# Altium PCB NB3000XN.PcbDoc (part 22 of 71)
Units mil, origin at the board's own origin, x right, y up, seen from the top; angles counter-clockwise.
Board outline 9527.56 x 6929.77 mil, 6 copper layers (Top Layer, GND+SHIELD, MidLayer1, MidLayer2, P2 - 3V3+5V0, Bottom Layer), stack 62.375 mil thick; 832 components, 1027 nets, 4655 pads, 4981 vias.
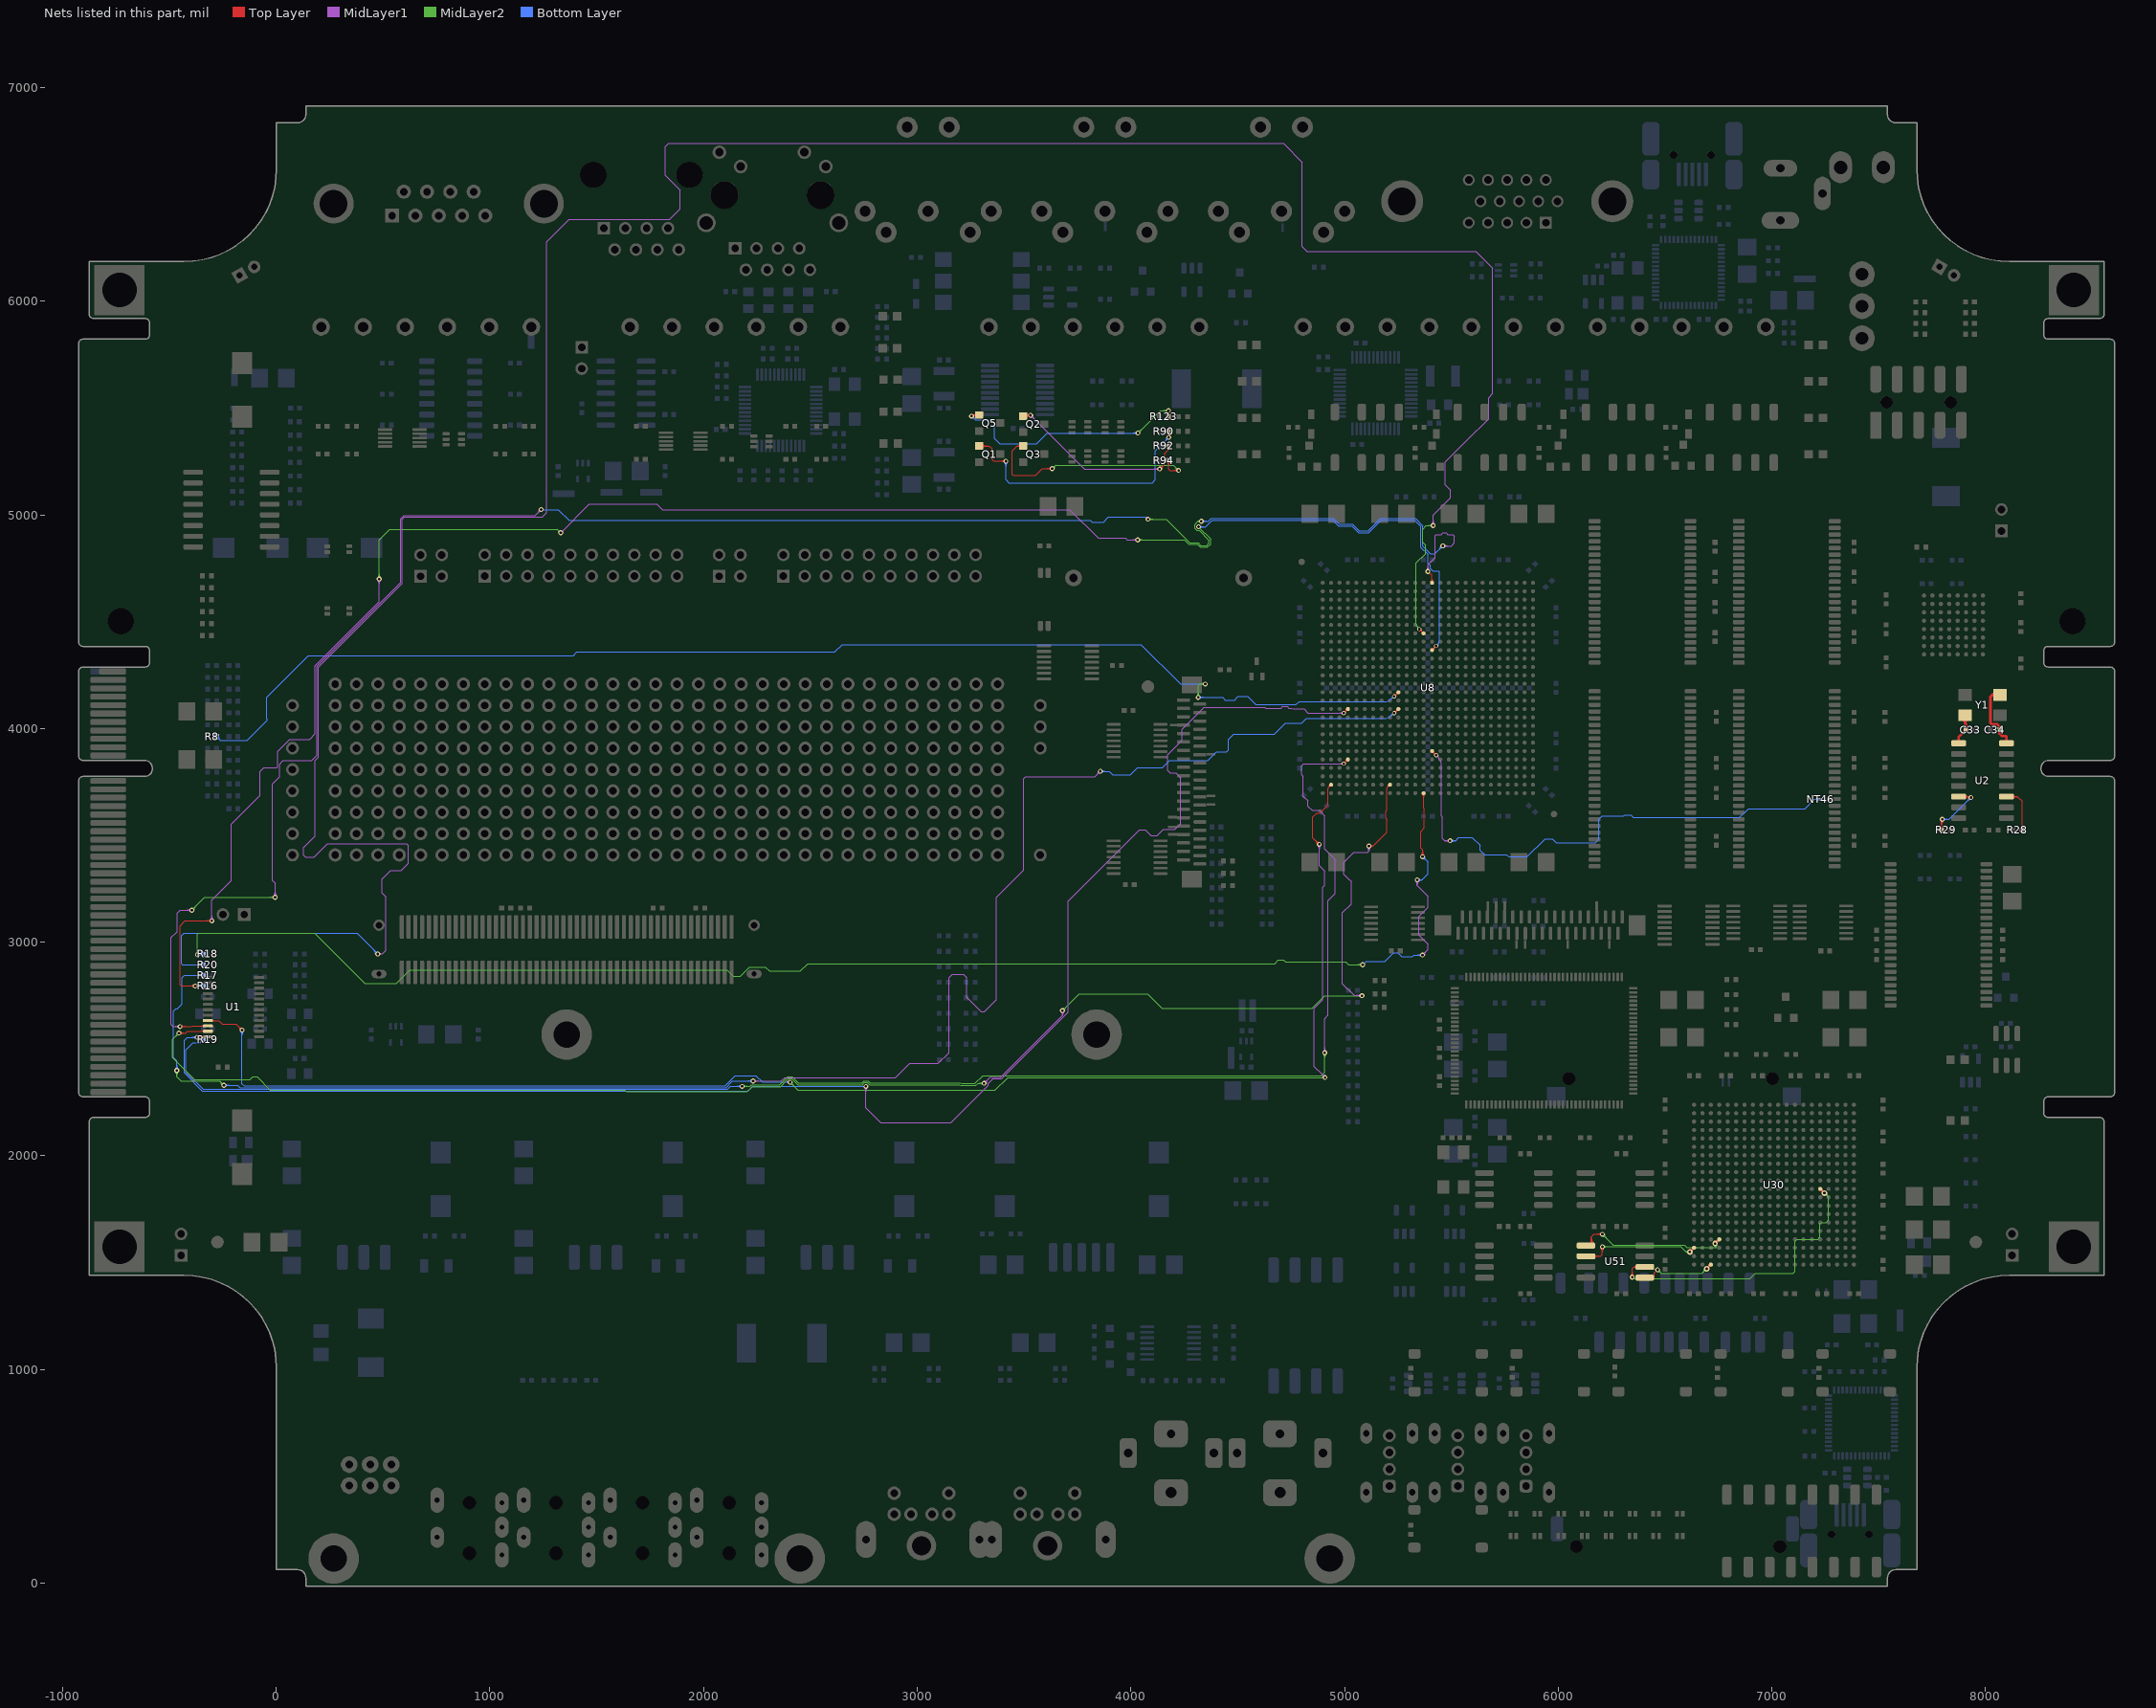
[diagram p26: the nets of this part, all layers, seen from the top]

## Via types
v1: diameter 23, hole 11.81, Top Layer to Bottom Layer, 3672 vias
v2: diameter 26, hole 11.81, Top Layer to Bottom Layer, 461 vias
v3: diameter 19, hole 11.81, Top Layer to Bottom Layer, tented both sides, 396 vias
v4: diameter 23.62, hole 11.81, Top Layer to Bottom Layer, 288 vias
v5: diameter 20, hole 11.81, Top Layer to Bottom Layer, 91 vias
v6: diameter 23, hole 11.81, Top Layer to Bottom Layer, tented both sides, 50 vias
v7: diameter 31, hole 11.81, Top Layer to Bottom Layer, 15 vias
v8: diameter 27.56, hole 11.81, Top Layer to Bottom Layer, tented both sides, 4 vias
v9: diameter 29, hole 11.81, Top Layer to Bottom Layer, 3 vias
v10: diameter 21, hole 11.81, Top Layer to Bottom Layer, 1 vias

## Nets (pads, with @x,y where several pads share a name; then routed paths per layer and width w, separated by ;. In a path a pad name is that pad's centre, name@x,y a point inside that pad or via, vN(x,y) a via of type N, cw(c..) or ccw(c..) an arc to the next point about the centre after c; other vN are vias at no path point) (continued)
BASEA: Q5.1 R123.2 | length 1608.2
  Top Layer w4: v1(3254.52,5462.71) v1@3259.22,5467.4 ; v1@3255.58,5461.65 cw(c3269.48,5447.75) 3269.48,5467.4 ; v1@3258.41,5458.82 cw(c3279.13,5438.1) Q5.1@3279.13,5467.4 ; v1@3261.24,5455.99 cw(c3288.79,5428.44) Q5.1@3288.79,5467.4 ; v1@3261.24,5469.43 ccw(c3266.13,5474.31) 3266.13,5467.4 ; Q5.1@3277.02,5458.25 ccw(c3259.22,5445.5) v1@3259.22,5467.4 ; Q5.1@3277.02,5476.55 cw(c3259.22,5489.3) v1@3259.22,5467.4 ; Q5.1@3280.28,5460.58 ccw(c3267,5451.07) 3267,5467.4 ccw(c3267,5483.73) Q5.1@3280.28,5474.22 ; Q5.1@3290.79,5467.4 v1@3259.22,5467.4 ; R123.2@4169.59,5467.08 ccw(c4153.66,5483.01) v1@4176.19,5483.01 ; v1@4171.65,5479.7 cw(c4167.48,5472.05) 4176.19,5472.05 ; R123.2@4172.42,5464.25 ccw(c4163.32,5473.35) 4176.19,5473.35 ; R123.2@4176.18,5460 4176.18,5472.04 ; 4176.19,5473.31 ccw(c4189,5473.31) R123.2@4179.94,5464.25 ; v1@4176.19,5482.97 ccw(c4198.66,5482.97) R123.2@4182.77,5467.08 ; v1(4176.19,5488.04) 4176.19,5472.05 ; R123.2@4178.17,5469.6 cw(c4178.7,5472.05) 4176.19,5472.05 ; R123.2@4178.15,5469.6 cw(c4178.68,5472.04) 4176.18,5472.04 ; v1@4180.73,5479.7 ccw(c4184.9,5472.05) 4176.19,5472.05 ; 4176.18,5472.04 cw(c4173.68,5472.04) 4174.21,5469.6 ccw(c4173.68,5472.05) 4176.19,5472.05
  MidLayer2 w4: v1(4033.19,5383.37) 4137.86,5488.04 v1(4176.19,5488.04) ; v1@4033.19,5388.87 ccw(c4033.19,5402.15) 4042.58,5392.76 ccw(c4051.97,5383.37) v1@4038.69,5383.37 ; v1@4033.19,5392.87 ccw(c4033.19,5415.81) 4049.41,5399.59 ccw(c4065.63,5383.37) v1@4042.69,5383.37 ; v1@4169.47,5481.32 ccw(c4153.26,5465.11) 4153.26,5488.04 ccw(c4153.26,5510.98) v1@4169.47,5494.76 ; v1@4172.3,5484.15 ccw(c4162.91,5474.76) 4162.91,5488.04 ccw(c4162.91,5501.32) v1@4172.3,5491.93
  Bottom Layer w4: v1@3254.52,5453.21 cw(c3254.52,5430.27) 3270.74,5446.49 cw(c3286.96,5462.71) v1@3264.02,5462.71 ; v1@3254.52,5457.21 cw(c3254.52,5443.93) 3263.91,5453.32 cw(c3273.3,5462.71) v1@3260.02,5462.71 ; v1(3254.52,5462.71) 3272.23,5445 3345,5445 3361.76,5428.24 3361.76,5358.24 3385.72,5334.28 3559.28,5334.28 3608.37,5383.37 v1(4033.19,5383.37) ; v1@4026.47,5376.66 ccw(c4010.26,5360.44) 4010.26,5383.37 ccw(c4010.26,5406.31) v1@4026.47,5390.09 ; v1@4029.3,5379.49 ccw(c4019.91,5370.1) 4019.91,5383.37 ccw(c4019.91,5396.65) v1@4029.3,5387.26
BASEB: Q1.1 R90.2 | length 1645.7
  Top Layer w4: Q1.1@3290.79,5322.4 3337.6,5322.4 3350,5310 3350,5260 3358.29,5251.71 v1(3415.19,5251.71) v1@3414.19,5252.71 ; Q1.1@3297.23,5316.95 cw(c3310.4,5303.77) 3310.4,5322.4 cw(c3310.4,5341.03) Q1.1@3297.23,5327.86 ; Q1.1@3300.06,5314.12 cw(c3320.06,5294.12) 3320.06,5322.4 cw(c3320.06,5350.69) Q1.1@3300.06,5330.69 ; Q1.1@3302.88,5311.29 cw(c3329.71,5284.46) 3329.71,5322.4 cw(c3329.71,5360.34) Q1.1@3302.88,5333.51 ; v1@3408.47,5244.99 ccw(c3392.26,5228.77) 3392.26,5251.71 ccw(c3392.26,5274.64) v1@3408.47,5258.43 ; v1@3411.3,5247.82 ccw(c3401.91,5238.43) 3401.91,5251.71 ccw(c3401.91,5264.99) v1@3411.3,5255.6 ; R90.2@4169.59,5384.59 cw(c4153.68,5368.68) 4176.18,5368.68 cw(c4198.68,5368.68) R90.2@4182.77,5384.59 ; v1@4170.81,5369.43 ccw(c4157.83,5382.4) R90.2@4176.18,5382.4 ; R90.2@4172.42,5387.41 cw(c4163.34,5378.33) 4176.18,5378.33 cw(c4189.02,5378.33) R90.2@4179.94,5387.41 ; 4176.18,5379.23 ccw(c4194.04,5379.23) v1@4181.41,5366.6 ; R90.2@4176.18,5388.89 ccw(c4203.7,5388.89) v1@4184.24,5369.43 ; R90.2@4176.18,5391.67 4176.18,5364.05 v1(4177.52,5362.71)
  Bottom Layer w4: v1@3408.47,5244.99 cw(c3392.26,5228.77) 3415.19,5228.77 cw(c3438.13,5228.77) v1@3421.91,5244.99 ; v1@3411.3,5247.82 cw(c3401.91,5238.43) 3415.19,5238.43 cw(c3428.47,5238.43) v1@3419.08,5247.82 ; v1(3415.19,5251.71) 3415.19,5164.81 3429.81,5150.19 4099.81,5150.19 4115,5165.38 4115,5300.18 v1(4177.52,5362.71) ; v1@4168.02,5362.71 cw(c4145.09,5362.71) 4161.31,5346.49 cw(c4177.52,5330.27) v1@4177.52,5353.21 ; v1@4172.02,5362.71 cw(c4158.75,5362.71) 4168.14,5353.32 cw(c4177.52,5343.93) v1@4177.52,5357.21
BASEC: Q2.1 R92.2 | length 1203.4
  Top Layer w4: Q2.1@3495.79,5462.4 v1@3526.22,5462.4 ; Q2.1@3497.19,5462.4 ccw(c3497.19,5500.04) v1@3523.81,5473.43 ; Q2.1@3506.51,5455.88 cw(c3518.72,5447.7) 3518.72,5462.4 cw(c3518.72,5477.11) Q2.1@3506.51,5468.92 ; Q2.1@3506.85,5462.4 ccw(c3506.85,5490.38) v1@3526.64,5470.6 ; Q2.1@3509.83,5453.66 cw(c3526.22,5442.68) v1@3526.22,5462.4 ; Q2.1@3509.83,5471.15 ccw(c3526.22,5482.13) v1@3526.22,5462.4 ; 3516.51,5462.4 ccw(c3516.51,5480.72) v1@3529.46,5467.77 ; 3517.98,5462.4 cw(c3517.98,5454.17) v1@3523.81,5459.99 ; v1(3530.52,5466.71) v1@3526.22,5462.4 ; v1(4135.19,5215.04) 4158.19,5238.04 4158.19,5287.72 4176.18,5305.71 ; v1@4135.19,5220.54 ccw(c4135.19,5233.82) 4144.58,5224.43 ccw(c4153.97,5215.04) v1@4140.69,5215.04 ; v1@4135.19,5224.54 ccw(c4135.19,5247.48) 4151.41,5231.26 ccw(c4167.63,5215.04) v1@4144.69,5215.04 ; R92.2@4171.12,5315.02 cw(c4165.09,5305.71) 4176.18,5305.71 ; R92.2@4176.18,5323.33 4176.18,5305.71 ; R92.2@4181.24,5315.02 ccw(c4187.27,5305.71) 4176.18,5305.71
  MidLayer1 w4: v1@3530.52,5457.21 cw(c3530.52,5434.27) 3546.74,5450.49 cw(c3562.96,5466.71) v1@3540.02,5466.71 ; v1@3530.52,5461.21 cw(c3530.52,5447.93) 3539.91,5457.32 cw(c3549.3,5466.71) v1@3536.02,5466.71 ; v1(3530.52,5466.71) 3782.19,5215.04 v1(4135.19,5215.04) ; v1@4128.47,5208.32 ccw(c4112.26,5192.11) 4112.26,5215.04 ccw(c4112.26,5237.98) v1@4128.47,5221.76 ; v1@4131.3,5211.15 ccw(c4121.91,5201.76) 4121.91,5215.04 ccw(c4121.91,5228.32) v1@4131.3,5218.93
BASED: Q3.1 R94.2 | length 1413.2
  Top Layer w4: Q3.1@3481.24,5314.47 ccw(c3467.4,5306.37) 3467.4,5322.4 ; Q3.1@3481.24,5330.34 cw(c3467.4,5338.43) 3467.4,5322.4 ; Q3.1@3484.69,5316.49 ccw(c3474.38,5310.45) 3474.38,5322.4 ccw(c3474.38,5334.35) Q3.1@3484.69,5328.32 ; Q3.1@3495.79,5322.4 3467.4,5322.4 ; v1@3625.14,5209.99 ccw(c3608.92,5193.77) 3608.92,5216.71 ccw(c3608.92,5239.64) v1@3625.14,5223.43 ; v1@3627.97,5212.82 ccw(c3618.58,5203.43) 3618.58,5216.71 ccw(c3618.58,5229.99) v1@3627.97,5220.6 ; v1(3631.86,5216.71) 3586.71,5216.71 3555,5185 3450,5185 3445,5190 3445,5300 3467.4,5322.4 ; R94.2@4169.59,5247.92 cw(c4153.68,5232.01) 4176.18,5232.01 cw(c4198.68,5232.01) R94.2@4182.77,5247.92 ; R94.2@4172.42,5250.75 cw(c4163.34,5241.67) 4176.18,5241.67 cw(c4189.02,5241.67) R94.2@4179.94,5250.75 ; R94.2@4176.18,5255 4176.18,5213.82 4181.63,5208.37 v1(4223.52,5208.37) ; v1@4216.81,5201.66 ccw(c4200.59,5185.44) 4200.59,5208.37 ccw(c4200.59,5231.31) v1@4216.81,5215.09 ; v1@4219.64,5204.49 ccw(c4210.25,5195.1) 4210.25,5208.37 ccw(c4210.25,5221.65) v1@4219.64,5212.26
  MidLayer2 w4: v1(3631.86,5216.71) 3648.52,5233.37 4198.52,5233.37 v1(4223.52,5208.37) ; v1@3631.86,5222.21 ccw(c3631.86,5235.49) 3641.25,5226.1 ccw(c3650.64,5216.71) v1@3637.36,5216.71 ; v1@3631.86,5226.21 ccw(c3631.86,5249.14) 3648.07,5232.93 ccw(c3664.29,5216.71) v1@3641.36,5216.71 ; v1@4214.02,5208.37 ccw(c4191.09,5208.37) 4207.31,5224.59 ccw(c4223.52,5240.81) v1@4223.52,5217.87 ; v1@4218.02,5208.37 ccw(c4204.75,5208.37) 4214.14,5217.76 ccw(c4223.52,5227.15) v1@4223.52,5213.87
BOOT_FLASH.DIN: U30.V20 U51.5 | length 550.9
  Top Layer w4: U51.5@6405.59,1430 6449.79,1430 ; U51.5@6446.62,1427.45 cw(c6449.79,1426.75) 6449.79,1430 ; U51.5@6446.62,1432.55 ccw(c6449.79,1433.25) 6449.79,1430 ; v1(6465.19,1466.71) 6449.79,1451.31 6449.79,1430
  Top Layer w8: v2(6695.04,1471.3) U30.V20@6714.72,1490.98 ; v2@6695.04,1480.3 ccw(c6695.04,1502.03) 6710.4,1486.66 ccw(c6725.77,1471.3) v2@6704.04,1471.3 ; U30.V20@6708.88,1490.98 cw(c6694.78,1490.98) 6704.75,1481.01 cw(c6714.72,1471.04) U30.V20@6714.72,1485.14
  MidLayer2 w4: v1@6465.19,1457.21 cw(c6465.19,1434.27) 6481.41,1450.49 cw(c6497.63,1466.71) v1@6474.69,1466.71 ; v1@6465.19,1461.21 cw(c6465.19,1447.93) 6474.58,1457.32 cw(c6483.97,1466.71) v1@6470.69,1466.71 ; v1(6465.19,1466.71) 6481.86,1450.04 6673.78,1450.04 v2(6695.04,1471.3) ; 6683.09,1459.35 ccw(c6671.14,1471.3) v2@6688.04,1471.3 ; 6683.09,1459.35 cw(c6695.04,1447.4) v2@6695.04,1464.3 ; v2@6684.04,1471.3 cw(c6657.48,1471.3) 6676.26,1452.52 cw(c6695.04,1433.75) v2@6695.04,1460.3
BOOT_FLASH.DOUT: U30.Y18 U51.2 | length 828.4
  Top Layer w4: U51.2@6130,1530 6200,1530 6206.86,1536.86 v1(6206.86,1574.37) ; U51.2@6165.03,1524.5 cw(c6178.31,1511.22) 6178.31,1530 cw(c6178.31,1548.78) U51.2@6165.03,1535.5 ; U51.2@6167.86,1521.67 cw(c6187.97,1501.56) 6187.97,1530 cw(c6187.97,1558.44) U51.2@6167.86,1538.33 ; v1@6200.14,1567.66 cw(c6183.92,1551.44) 6206.86,1551.44 cw(c6229.79,1551.44) v1@6213.57,1567.66 ; v1@6202.97,1570.49 cw(c6193.58,1561.1) 6206.86,1561.1 cw(c6220.14,1561.1) v1@6210.75,1570.49
  Top Layer w8: v2(6616.3,1550.04) U30.Y18@6635.98,1569.72 ; v2@6616.3,1559.04 ccw(c6616.3,1580.77) 6631.66,1565.4 ccw(c6647.03,1550.04) v2@6625.3,1550.04 ; U30.Y18@6630.14,1569.72 cw(c6616.04,1569.72) 6626.01,1559.75 cw(c6635.98,1549.78) U30.Y18@6635.98,1563.88
  MidLayer2 w4: v1(6206.86,1574.37) 6574.19,1574.37 6598.52,1550.04 ; v1@6210.75,1570.49 cw(c6220.14,1561.1) 6220.14,1574.37 cw(c6220.14,1587.65) v1@6210.75,1578.26 ; v1@6213.57,1567.66 cw(c6229.79,1551.44) 6229.79,1574.37 cw(c6229.79,1597.31) v1@6213.57,1581.09 ; v2@6606.45,1545.13 ccw(c6598.52,1541.18) 6598.52,1550.04 ; v2@6606.45,1554.95 cw(c6598.52,1558.9) 6598.52,1550.04 ; v2(6616.3,1550.04) 6598.52,1550.04
BOOT_FLASH.FLASH_CS_N: U30.U17 U51.1 | length 1022.1
  Top Layer w4: U51.1@6130,1580 6154.52,1580 6154.52,1619.52 ; U51.1@6151.2,1588.33 ccw(c6143.17,1596.36) 6154.52,1596.36 ; 6154.52,1600.68 ccw(c6179.49,1600.68) U51.1@6162.15,1582.72 ; 6154.52,1610.1 ccw(c6188.58,1610.1) U51.1@6164.93,1585.6 ; U51.1@6167.71,1588.48 cw(c6197.67,1619.52) 6154.52,1619.52 ; v1@6200.14,1626.66 ccw(c6183.92,1610.44) 6183.92,1633.37 ccw(c6183.92,1656.31) v1@6200.14,1640.09 ; v1@6202.97,1629.49 ccw(c6193.58,1620.1) 6193.58,1633.37 ccw(c6193.58,1646.65) v1@6202.97,1637.26 ; v1(6206.86,1633.37) 6168.37,1633.37 6154.52,1619.52
  Top Layer w8: v2(6734.41,1589.41) U30.U17@6754.09,1609.09 ; v2@6734.41,1598.41 ccw(c6734.41,1620.14) 6749.77,1604.77 ccw(c6765.14,1589.41) v2@6743.41,1589.41 ; U30.U17@6748.25,1609.09 cw(c6734.15,1609.09) 6744.12,1599.12 cw(c6754.09,1589.15) U30.U17@6754.09,1603.25
  MidLayer2 w4: v1@6206.86,1623.87 cw(c6206.86,1600.94) 6223.07,1617.16 cw(c6239.29,1633.37) v1@6216.36,1633.37 ; v1@6206.86,1627.87 cw(c6206.86,1614.6) 6216.25,1623.99 cw(c6225.64,1633.37) v1@6212.36,1633.37 ; v1(6206.86,1633.37) 6257.52,1582.71 6590.19,1582.71 6602.86,1570.04 6738.52,1570.04 6740.19,1571.71 6740.19,1589.41 v2(6734.41,1589.41) ; v2@6733.27,1578.47 cw(c6732.47,1570.79) 6740.19,1570.79 ; v2@6733.68,1582.45 cw(c6732.93,1575.23) 6740.19,1575.23 ; 6740.19,1576.81 cw(c6747.01,1576.81) v2@6742.19,1581.63
BOOT_FLASH.SCLK: U30.E11 U51.6 | length 1649.6
  Top Layer w4: v1@6339.47,1439.09 ccw(c6323.26,1455.31) 6346.19,1455.31 ccw(c6369.13,1455.31) v1@6352.91,1439.09 ; v1@6342.3,1436.26 ccw(c6332.91,1445.65) 6346.19,1445.65 ccw(c6359.47,1445.65) v1@6350.08,1436.26 ; v1(6346.19,1432.37) 6346.19,1472 6354.19,1480 ; U51.6@6366.23,1473.52 ccw(c6354.19,1465.58) 6354.19,1480 ; U51.6@6366.23,1486.48 cw(c6354.19,1494.42) 6354.19,1480 ; U51.6@6369.57,1475.72 ccw(c6361.62,1470.48) 6361.62,1480 ccw(c6361.62,1489.52) U51.6@6369.57,1484.28 ; U51.6@6405.59,1480 6354.19,1480
  Top Layer w8: U30.E11@7226.54,1839.47 cw(c7226.54,1825.37) 7236.51,1835.34 cw(c7246.48,1845.31) U30.E11@7232.38,1845.31 ; U30.E11@7226.54,1845.31 v2(7246.22,1825.63) ; v2@7237.22,1825.63 ccw(c7215.49,1825.63) 7230.86,1840.99 ccw(c7246.22,1856.36) v2@7246.22,1834.63
  MidLayer2 w4: v1(6346.19,1432.37) 6353.52,1425.04 6898.52,1425.04 6923.52,1450.04 7100.19,1450.04 7108.52,1458.37 7108.52,1600 7118.3,1609.78 7214.78,1609.78 7225.85,1620.85 7225.85,1685.85 7228.52,1688.52 7254.09,1688.52 7265.22,1699.65 7265.22,1806.63 v2(7246.22,1825.63) ; v2@7246.22,1814.63 cw(c7246.22,1788.07) 7265,1806.85 cw(c7283.78,1825.63) v2@7257.22,1825.63 ; v2@7246.22,1818.63 cw(c7246.22,1801.73) 7258.17,1813.68 cw(c7270.12,1825.63) v2@7253.22,1825.63
BUS_SDRAM_FEEDBACK: NT46.1 U8.AA14 | length 2690.9
  Top Layer w4: U8.AA14@5409.69,3887.22 cw(c5409.69,3869.12) 5422.49,3881.92 cw(c5435.29,3894.72) U8.AA14@5417.19,3894.72 ; U8.AA14@5409.69,3887.38 cw(c5409.69,3869.66) 5422.22,3882.19 cw(c5434.75,3894.72) U8.AA14@5417.03,3894.72 ; U8.AA14@5409.69,3894.72 v3(5429.37,3875.04) ; 5416.57,3887.84 cw(c5403.76,3875.04) 5421.87,3875.04 ccw(c5403.76,3875.04) 5416.57,3887.84 ; 5416.57,3887.84 ccw(c5429.37,3900.65) 5429.37,3882.54 cw(c5429.37,3900.65) 5416.57,3887.84
  MidLayer1 w4: v3@5428.72,3867.57 cw(c5427.14,3849.53) 5441.01,3861.17 ; v3@5436.84,3874.39 ccw(c5454.88,3872.81) 5441.01,3861.17 ; v1@5487.81,3468.32 ccw(c5471.59,3452.11) 5471.59,3475.04 ccw(c5471.59,3497.98) v1@5487.81,3481.76 ; v1@5490.64,3471.15 ccw(c5481.25,3461.76) 5481.25,3475.04 ccw(c5481.25,3488.32) v1@5490.64,3478.93 ; v1(5494.52,3475.04) 5469.96,3475.04 5458.5,3486.5 5458.5,3585.18 5453.23,3590.45 5453.23,3660 5453.23,3670 5453.23,3738.04 5453.23,3812.16 5453.23,3831.66 ccw(c5411.5,3831.66) 5441.01,3861.17
  Bottom Layer w4: v1(5494.52,3475.04) 5520.04,3475.04 5535,3490 5597.27,3490 5633.9,3453.37 5633.9,3429.79 5654.6,3409.08 5759.13,3409.08 5768.17,3400.04 5855,3400.04 5938.83,3483.87 5973.34,3483.87 5991.17,3466.04 6173.52,3466.04 6190.19,3482.71 6190.19,3575.04 6206.86,3591.71 6306.86,3591.71 6310.15,3595 6340,3595 6351.63,3583.37 6848.52,3583.37 6890.19,3625.04 7155.04,3625.04 7199,3669 NT46.1@7219,3669 ; v1@5498.41,3471.15 cw(c5507.8,3461.76) 5507.8,3475.04 cw(c5507.8,3488.32) v1@5498.41,3478.93 ; v1@5501.24,3468.32 cw(c5517.46,3452.11) 5517.46,3475.04 cw(c5517.46,3497.98) v1@5501.24,3481.76 ; NT46.1@7211.67,3666.17 ccw(c7204.84,3659.34) 7204.84,3669 ccw(c7204.84,3678.66) NT46.1@7211.67,3671.83
BUZZER: R8.1 U8.P10 | length 6445.2
  Top Layer w4: v3(5232.52,4150.63) U8.P10@5252.2,4170.31 ; U8.P10@5244.7,4170.31 cw(c5226.6,4170.31) 5239.4,4157.51 cw(c5252.2,4144.71) U8.P10@5252.2,4162.81 ; U8.P10@5244.86,4170.31 cw(c5227.14,4170.31) 5239.67,4157.78 cw(c5252.2,4145.25) U8.P10@5252.2,4162.97 ; 5245.32,4163.43 cw(c5232.52,4176.24) 5232.52,4158.13 ccw(c5232.52,4176.24) 5245.32,4163.43 ; 5245.32,4163.43 ccw(c5258.13,4150.63) 5240.02,4150.63 cw(c5258.13,4150.63) 5245.32,4163.43
  MidLayer2 w4: v1@4308.47,4152.43 ccw(c4292.26,4168.64) 4315.19,4168.64 ccw(c4338.13,4168.64) v1@4321.91,4152.43 ; v1@4311.3,4149.6 ccw(c4301.91,4158.99) 4315.19,4158.99 ccw(c4328.47,4158.99) v1@4319.08,4149.6 ; v1(4315.19,4145.71) 4315.19,4200.19 4323.37,4208.37 v1(4348.52,4208.37) ; v1@4341.81,4201.66 ccw(c4325.59,4185.44) 4325.59,4208.37 ccw(c4325.59,4231.31) v1@4341.81,4215.09 ; v1@4344.64,4204.49 ccw(c4335.25,4195.1) 4335.25,4208.37 ccw(c4335.25,4221.65) v1@4344.64,4212.26
  Bottom Layer w4: R8.1@-278.82,3952.46 cw(c-278.82,3928.78) -262.07,3945.52 ; R8.1@-278.82,3956.46 cw(c-278.82,3942.43) R8.1@-268.9,3952.35 ; R8.1@-278.82,3962.27 -261.01,3944.46 -136.08,3944.46 -42.65,4037.9 -42.65,4044.19 -43.48,4045.02 -43.48,4146.73 151.51,4341.71 1390.19,4341.71 1406.86,4358.37 2615,4358.37 2648.67,4392.04 4048.23,4392.04 4231.9,4208.37 v1(4348.52,4208.37) ; R8.1@-273.5,3961.78 ccw(c-261.85,3961.78) R8.1@-270.09,3953.54 ; R8.1@-269.5,3961.78 ccw(c-248.19,3961.78) -263.26,3946.71 ; v1(4315.19,4145.71) 4429.33,4145.71 4441.33,4133.71 4485.17,4133.71 4501.5,4150.04 4545.54,4150.04 4583.67,4111.92 4773.38,4111.92 4788.23,4126.77 4860,4126.77 4870,4126.77 5076.1,4126.77 5095.52,4126.77 5169.64,4126.77 5189.14,4126.77 ccw(c5189.14,4168.5) 5218.65,4138.99 ; v1@4319.08,4141.82 cw(c4328.47,4132.43) 4328.47,4145.71 cw(c4328.47,4158.99) v1@4319.08,4149.6 ; v1@4321.91,4138.99 cw(c4338.13,4122.77) 4338.13,4145.71 cw(c4338.13,4168.64) v1@4321.91,4152.43 ; v1@4341.81,4201.66 ccw(c4325.59,4185.44) 4325.59,4208.37 ccw(c4325.59,4231.31) v1@4341.81,4215.09 ; v1@4344.64,4204.49 ccw(c4335.25,4195.1) 4335.25,4208.37 ccw(c4335.25,4221.65) v1@4344.64,4212.26 ; v3@5225.05,4151.28 cw(c5207.01,4152.86) 5218.65,4138.99 ; v3@5231.87,4143.16 ccw(c5230.29,4125.12) 5218.65,4138.99
CLK_ADJ_X1: C33.1 U2.1 Y1.1 | length 268.3
  Top Layer w12: U2.1@7868.67,3936.84 ccw(c7855.39,3950.12) 7874.17,3950.12 ccw(c7892.95,3950.12) U2.1@7879.67,3936.84 ; U2.1@7874.17,3931.34 7874.17,3959.84 C33.1@7909.33,3995 7909.33,4020 7904.88,4024.45 ; Y1.1@7893.79,4044.08 cw(c7881.97,4024.45) 7904.88,4024.45 ; C33.1@7903.52,3995 cw(c7889.49,3995) 7899.41,3985.08 cw(c7909.33,3975.16) C33.1@7909.33,3989.19 ; Y1.1@7904.88,4062.5 7904.88,4024.45 ; C33.1@7905.22,3999.11 ccw(c7895.3,4009.03) 7909.33,4009.03 ccw(c7923.36,4009.03) C33.1@7913.44,3999.11 ; Y1.1@7915.97,4044.08 ccw(c7927.79,4024.45) 7904.88,4024.45
CLK_ADJ_X2: C34.1 U2.16 Y1.3 | length 554.6
  Top Layer w12: 8024.1,4150.07 cw(c8040.99,4133.17) Y1.3@8057.37,4150.58 ; 8029.17,4155.15 cw(c8050.06,4134.26) Y1.3@8065.16,4159.65 ; 8032.85,4158.82 cw(c8049.48,4142.19) Y1.3@8065.59,4159.32 ; Y1.3@8044.06,4149.17 ccw(c8031.53,4143.91) 8031.53,4157.5 ; Y1.3@8044.06,4165.83 cw(c8031.53,4171.09) 8031.53,4157.5 ; C34.1@8061.56,3990.89 cw(c8051.64,3980.97) 8065.67,3980.97 cw(c8079.7,3980.97) C34.1@8069.78,3990.89 ; C34.1@8061.56,3999.11 ccw(c8051.64,4009.03) 8065.67,4009.03 ccw(c8079.7,4009.03) C34.1@8069.78,3999.11 ; 8066.65,4008.35 cw(c8054.02,3995.72) C34.1@8071.85,3994.62 ; Y1.3@8067.88,4157.5 8031.52,4157.5 ; U2.16@8093.08,3936.84 ccw(c8079.8,3950.12) 8098.58,3950.12 ccw(c8117.36,3950.12) U2.16@8104.08,3936.84 ; U2.16@8098.58,3931.34 8098.58,3961.42 8095,3965 8077.29,3965 8065.67,3976.62 C34.1@8065.67,3995 8065.67,4009.33 8055,4020 8030,4020 8023.52,4026.48 8023.52,4149.5 8031.52,4157.5
CLK_FIXED#: R29.2 U2.6 | length 669.3
  Top Layer w4: R29.2@7787.23,3532.08 ccw(c7771.32,3547.99) 7793.82,3547.99 ccw(c7816.32,3547.99) R29.2@7800.41,3532.08 ; R29.2@7790.06,3529.25 ccw(c7780.98,3538.33) 7793.82,3538.33 ccw(c7806.66,3538.33) R29.2@7797.58,3529.25 ; v1@7790.81,3568.32 cw(c7783.53,3561.05) 7793.82,3561.05 ; R29.2@7793.82,3525 7793.82,3571.34 v1(7797.52,3575.04) ; 7793.82,3543.16 cw(c7829.4,3543.16) v1@7804.24,3568.32 ; 7793.82,3552.82 cw(c7819.75,3552.82) v1@7801.41,3571.15 ; 7793.82,3562.47 cw(c7810.09,3562.47) v1@7798.58,3573.98 ; U2.6@7874.17,3681.34 v1@7923.82,3681.34 ; U2.6@7899.35,3681.34 cw(c7899.35,3644.87) v1@7925.14,3670.66 ; U2.6@7901.39,3675.9 cw(c7914.31,3663.26) 7914.31,3681.34 cw(c7914.31,3699.42) U2.6@7901.39,3686.78 ; U2.6@7904.25,3673.1 cw(c7923.82,3653.97) v1@7923.82,3681.34 ; U2.6@7904.25,3689.57 ccw(c7923.82,3708.71) v1@7923.82,3681.34 ; U2.6@7909.01,3681.34 cw(c7909.01,3654.53) v1@7927.97,3673.49 ; 7918.49,3681.34 ccw(c7918.49,3690.74) v1@7925.14,3684.09 ; 7918.67,3681.34 cw(c7918.67,3664.18) v1@7930.8,3676.31 ; v1(7931.86,3677.37) 7927.52,3681.71 7924.19,3681.71 v1@7923.82,3681.34
  Bottom Layer w4: v1(7797.52,3575.04) 7829.52,3575.04 v1(7931.86,3677.37) ; v1@7801.41,3571.15 cw(c7810.8,3561.76) 7810.8,3575.04 cw(c7810.8,3588.32) v1@7801.41,3578.93 ; v1@7804.24,3568.32 cw(c7820.46,3552.11) 7820.46,3575.04 cw(c7820.46,3597.98) v1@7804.24,3581.76 ; v1@7922.36,3677.37 cw(c7899.42,3677.37) 7915.64,3661.16 cw(c7931.86,3644.94) v1@7931.86,3667.87 ; v1@7926.36,3677.37 cw(c7913.08,3677.37) 7922.47,3667.99 cw(c7931.86,3658.6) v1@7931.86,3671.87
CLK_PROG#: R28.2 U2.11 | length 346.5
  Top Layer w4: U2.11@8098.58,3681.34 8150.56,3681.34 8171.18,3660.72 R28.2@8171.18,3525 ; U2.11@8125.74,3675.84 cw(c8139.02,3662.56) 8139.02,3681.34 cw(c8139.02,3700.12) U2.11@8125.74,3686.84 ; U2.11@8128.57,3673.01 cw(c8148.67,3652.9) 8148.67,3681.34 cw(c8148.67,3709.78) U2.11@8128.57,3689.67 ; R28.2@8164.59,3532.08 ccw(c8148.68,3547.99) 8171.18,3547.99 ccw(c8193.68,3547.99) R28.2@8177.77,3532.08 ; R28.2@8167.42,3529.25 ccw(c8158.34,3538.33) 8171.18,3538.33 ccw(c8184.02,3538.33) R28.2@8174.94,3529.25
CODEC.I2S_BCLK: R16.2 U8.J14 | length 9481.9
  Top Layer w4: v1@-385.9,2788.28 ccw(c-402.11,2772.06) -402.11,2795 ccw(c-402.11,2817.93) v1@-385.9,2801.72 ; v1@-383.07,2791.11 ccw(c-392.46,2781.72) -392.46,2795 ccw(c-392.46,2808.28) v1@-383.07,2798.89 ; v1(-379.18,2795) -445,2795 -450,2800 -450,3076.52 -426.48,3100.04 v1(-301.48,3100.04) ; v1@-308.19,3093.32 ccw(c-324.41,3077.11) -324.41,3100.04 ccw(c-324.41,3122.98) v1@-308.19,3106.76 ; v1@-305.36,3096.15 ccw(c-314.75,3086.76) -314.75,3100.04 ccw(c-314.75,3113.32) v1@-305.36,3103.93 ; U8.J14@5409.69,4367.17 v3(5429.37,4386.85) ; U8.J14@5409.69,4374.51 ccw(c5409.69,4392.23) 5422.22,4379.7 ccw(c5434.75,4367.17) U8.J14@5417.03,4367.17 ; U8.J14@5409.69,4374.67 ccw(c5409.69,4392.77) 5422.49,4379.97 ccw(c5435.29,4367.17) U8.J14@5417.19,4367.17 ; 5416.57,4374.05 cw(c5429.37,4361.24) 5429.37,4379.35 ccw(c5429.37,4361.24) 5416.57,4374.05 ; 5416.57,4374.05 ccw(c5403.76,4386.85) 5421.87,4386.85 cw(c5403.76,4386.85) 5416.57,4374.05
  MidLayer1 w4: v1@-308.19,3106.76 ccw(c-324.41,3122.98) -301.48,3122.98 ccw(c-278.54,3122.98) v1@-294.76,3106.76 ; v1@-305.36,3103.93 ccw(c-314.75,3113.32) -301.48,3113.32 ccw(c-288.2,3113.32) v1@-297.59,3103.93 ; v1(-301.48,3100.04) -301.48,3197.06 -210,3288.54 -210,3552.37 -80.21,3682.16 -75.3,3687.07 -75.3,3790 ; -75,3790 -75,3800 -58.29,3816.71 1.71,3816.71 7.19,3822.19 7.19,3893.67 63.56,3950.04 156.86,3950.04 181.86,3975.04 181.86,4294.69 481.86,4594.69 v1(481.86,4700.04) ; v1@475.14,4693.32 cw(c458.92,4677.11) 481.86,4677.11 cw(c504.79,4677.11) v1@488.57,4693.32 ; v1@477.97,4696.15 cw(c468.58,4686.76) 481.86,4686.76 cw(c495.14,4686.76) v1@485.75,4696.15 ; v1(1331.86,4916.71) 1465.19,5050.04 1781.86,5050.04 1806.86,5025.04 3713.65,5025.04 3846.98,4891.71 3974.51,4891.71 3982.84,4883.37 v1(4031.86,4883.37) ; v1@1331.86,4922.21 ccw(c1331.86,4935.49) 1341.25,4926.1 ccw(c1350.64,4916.71) v1@1337.36,4916.71 ; v1@1331.86,4926.21 ccw(c1331.86,4949.14) 1348.07,4932.93 ccw(c1364.29,4916.71) v1@1341.36,4916.71 ; v1@4025.14,4876.66 ccw(c4008.92,4860.44) 4008.92,4883.37 ccw(c4008.92,4906.31) v1@4025.14,4890.09 ; v1@4027.97,4879.49 ccw(c4018.58,4870.1) 4018.58,4883.37 ccw(c4018.58,4896.65) v1@4027.97,4887.26
  MidLayer2 w4: v1@475.14,4706.76 ccw(c458.92,4722.98) 481.86,4722.98 ccw(c504.79,4722.98) v1@488.57,4706.76 ; v1@477.97,4703.93 ccw(c468.58,4713.32) 481.86,4713.32 ccw(c495.14,4713.32) v1@485.75,4703.93 ; v1(481.86,4700.04) 481.86,4883.37 531.86,4933.37 1315.19,4933.37 v1(1331.86,4916.71) ; v1@1322.36,4916.71 ccw(c1299.42,4916.71) 1315.64,4932.93 ccw(c1331.86,4949.14) v1@1331.86,4926.21 ; v1@1326.36,4916.71 ccw(c1313.08,4916.71) 1322.47,4926.1 ccw(c1331.86,4935.49) v1@1331.86,4922.21 ; v1(4031.86,4883.37) 4250.31,4883.37 4271.69,4862 4311.56,4862 4324.69,4848.87 4359.09,4848.87 4374.02,4863.81 4374.02,4887.35 v1(4316.85,4944.52) ; v1@4035.75,4879.49 cw(c4045.14,4870.1) 4045.14,4883.37 cw(c4045.14,4896.65) v1@4035.75,4887.26 ; v1@4038.57,4876.66 cw(c4054.79,4860.44) 4054.79,4883.37 cw(c4054.79,4906.31) v1@4038.57,4890.09
  Bottom Layer w4: v1(-379.18,2795) R16.2@-341.18,2795 ; v1@-375.29,2791.11 cw(c-365.9,2781.72) -365.9,2795 cw(c-365.9,2808.28) v1@-375.29,2798.89 ; v1@-372.46,2788.28 cw(c-356.24,2772.06) -356.24,2795 cw(c-356.24,2817.93) v1@-372.46,2801.72 ; R16.2@-347.77,2788.41 ccw(c-363.68,2772.5) -363.68,2795 ccw(c-363.68,2817.5) R16.2@-347.77,2801.59 ; R16.2@-344.94,2791.24 ccw(c-354.02,2782.16) -354.02,2795 ccw(c-354.02,2807.84) R16.2@-344.94,2798.76 ; v1(4316.85,4944.52) 4349.48,4944.52 4380.67,4975.71 4944.9,4975.71 4972.06,4948.54 5034.33,4948.54 5066.17,4916.71 5113.82,4916.71 5172.15,4975.04 5328.23,4975.04 5356.86,4946.41 5356.86,4848.37 5390.19,4815.04 5390.19,4773.81 5402,4762 5402,4749 5414,4737 5440,4737 5444.88,4732.12 5444.88,4720 5444.88,4710 5444.88,4668 ; v1@4320.74,4940.63 cw(c4330.13,4931.25) 4330.13,4944.52 cw(c4330.13,4957.8) v1@4320.74,4948.41 ; v1@4323.57,4937.81 cw(c4339.79,4921.59) 4339.79,4944.52 cw(c4339.79,4967.46) v1@4323.57,4951.24 ; v3@5428.72,4394.32 ccw(c5427.14,4412.36) 5441.01,4400.72 ccw(c5454.88,4389.08) v3@5436.84,4387.5 ; 5440.76,4400.43 ccw(c5430.83,4410.36) 5444.88,4410.36 5444.88,4503.9 5444.88,4668 ; 5444.88,4675 5444.88,4668
CODEC.I2S_DIN: R17.2 U8.T10 | length 8686.8
  Top Layer w4: v3(5232.52,4071.89) U8.T10@5252.2,4091.57 ; U8.T10@5244.7,4091.57 cw(c5226.6,4091.57) 5239.4,4078.77 cw(c5252.2,4065.97) U8.T10@5252.2,4084.07 ; U8.T10@5244.86,4091.57 cw(c5227.14,4091.57) 5239.67,4079.04 cw(c5252.2,4066.51) U8.T10@5252.2,4084.23 ; 5245.32,4084.69 cw(c5232.52,4097.5) 5232.52,4079.39 ccw(c5232.52,4097.5) 5245.32,4084.69 ; 5245.32,4084.69 ccw(c5258.13,4071.89) 5240.02,4071.89 cw(c5258.13,4071.89) 5245.32,4084.69
  MidLayer1 w4: v1(2231.86,2350.04) 2363.54,2350.04 2380,2366.5 2898.13,2366.5 2965,2433.37 3098.52,2433.37 3148.52,2483.37 3148.52,2833.37 3165.19,2850.04 3215.19,2850.04 3231.86,2833.37 3231.86,2741.71 3298.52,2675.04 3315.19,2675.04 3371,2730.85 3371,3211 3497.52,3337.52 3497.52,3765.1 3507.47,3775.04 3832.19,3775.04 v1(3857.19,3800.04) ; v1@2235.75,2346.15 cw(c2245.14,2336.76) 2245.14,2350.04 cw(c2245.14,2363.32) v1@2235.75,2353.93 ; v1@2238.57,2343.32 cw(c2254.79,2327.11) 2254.79,2350.04 cw(c2254.79,2372.98) v1@2238.57,2356.76 ; v1@3847.69,3800.04 cw(c3824.76,3800.04) 3840.97,3783.82 cw(c3857.19,3767.61) v1@3857.19,3790.54 ; v1@3851.69,3800.04 cw(c3838.41,3800.04) 3847.8,3790.65 cw(c3857.19,3781.26) v1@3857.19,3794.54
  MidLayer2 w4: v4@-471.94,2393.06 cw(c-488.69,2376.31) -465,2376.31 cw(c-441.31,2376.31) v4@-458.06,2393.06 ; v4@-469.11,2395.89 cw(c-479.03,2385.97) -465,2385.97 cw(c-450.97,2385.97) v4@-460.89,2395.89 ; v4(-465,2400) -465,2370.25 -444.46,2349.71 -264.71,2349.71 v4(-245,2330) ; v4@-254.81,2330 ccw(c-278.5,2330) -261.75,2346.75 ccw(c-245,2363.5) v4@-245,2339.81 ; v4@-250.81,2330 ccw(c-264.84,2330) -254.92,2339.92 ccw(c-245,2349.84) v4@-245,2335.81
  Bottom Layer w4: v4@-471.94,2406.94 ccw(c-488.69,2423.69) -465,2423.69 ccw(c-441.31,2423.69) v4@-458.06,2406.94 ; v4@-469.11,2404.11 ccw(c-479.03,2414.03) -465,2414.03 ccw(c-450.97,2414.03) v4@-460.89,2404.11 ; v4(-465,2400) -465,2445 -480,2460 -480,2677.66 -470,2687.66 -462.34,2687.66 -440,2710 -440,2835 -430,2845 R17.2@-341.18,2845 ; R17.2@-347.77,2838.41 ccw(c-363.68,2822.5) -363.68,2845 ccw(c-363.68,2867.5) R17.2@-347.77,2851.59 ; R17.2@-344.94,2841.24 ccw(c-354.02,2832.16) -354.02,2845 ccw(c-354.02,2857.84) R17.2@-344.94,2848.76 ; v4(-245,2330) -180,2330 -170.02,2320.02 2104.61,2320.02 2134.63,2350.04 v1(2231.86,2350.04) ; v4@-240.89,2325.89 cw(c-230.97,2315.97) -230.97,2330 cw(c-230.97,2344.03) v4@-240.89,2334.11 ; v4@-238.06,2323.06 cw(c-221.31,2306.31) -221.31,2330 cw(c-221.31,2353.69) v4@-238.06,2336.94 ; v1@2225.14,2343.32 ccw(c2208.92,2327.11) 2208.92,2350.04 ccw(c2208.92,2372.98) v1@2225.14,2356.76 ; v1@2227.97,2346.15 ccw(c2218.58,2336.76) 2218.58,2350.04 ccw(c2218.58,2363.32) v1@2227.97,2353.93 ; v1(3857.19,3800.04) 3898.33,3800.04 3915,3783.37 3998.52,3783.37 4031.86,3816.71 4148.52,3816.71 4182.19,3850.37 4360.17,3850.37 4400.84,3891.04 4430,3891.04 4448.52,3891.04 4456.86,3899.37 4456.86,3950.04 4481.19,3974.37 4672.86,3974.37 4723.52,4025.04 4800,4025.04 4822.99,4048.03 4860,4048.03 4870,4048.03 5076.1,4048.03 5095.52,4048.03 5169.64,4048.03 5189.14,4048.03 ccw(c5189.14,4089.76) 5218.65,4060.25 ; v1@3861.08,3796.15 cw(c3870.47,3786.76) 3870.47,3800.04 cw(c3870.47,3813.32) v1@3861.08,3803.93 ; v1@3863.91,3793.32 cw(c3880.13,3777.11) 3880.13,3800.04 cw(c3880.13,3822.98) v1@3863.91,3806.76 ; v3@5225.05,4072.54 cw(c5207.01,4074.12) 5218.65,4060.25 ; v3@5231.87,4064.42 ccw(c5230.29,4046.38) 5218.65,4060.25
CODEC.I2S_DOUT: R19.2 U8.AB4 | length 7874.1
  Top Layer w4: v3(4996.3,3835.67) U8.AB4@5015.98,3855.35 ; U8.AB4@5008.48,3855.35 cw(c4990.38,3855.35) 5003.18,3842.55 cw(c5015.98,3829.75) U8.AB4@5015.98,3847.85 ; U8.AB4@5008.64,3855.35 cw(c4990.92,3855.35) 5003.45,3842.82 cw(c5015.98,3830.29) U8.AB4@5015.98,3848.01 ; 5009.1,3848.47 cw(c4996.3,3861.28) 4996.3,3843.17 ccw(c4996.3,3861.28) 5009.1,3848.47 ; 5009.1,3848.47 ccw(c5021.91,3835.67) 5003.8,3835.67 cw(c5021.91,3835.67) 5009.1,3848.47
  MidLayer1 w4: v1@4901.14,2489.09 ccw(c4887.34,2502.9) 4906.86,2502.9 ; 4906.86,2498.07 ccw(c4923.55,2498.07) v1@4911.75,2486.26 ; 4906.86,2507.72 ccw(c4933.21,2507.72) v1@4914.57,2489.09 ; v1(4907.86,2482.37) 4906.86,2483.37 4906.86,2641.71 4923.52,2658.37 4923.52,3194.69 4956.86,3228.02 4956.86,3386.36 4907.52,3435.69 4907.52,3591.71 4882.52,3616.71 4848.52,3616.71 4828.52,3636.71 4828.52,3661.71 4806.86,3683.37 4806.86,3776.04 4799.52,3783.37 4799.52,3826.04 4809.15,3835.67 4860,3835.67 4870,3835.67 4918.62,3835.67 v3(4996.3,3835.67) ; v3@4991.11,3830.48 ccw(c4978.57,3817.94) 4978.57,3835.67 ccw(c4978.57,3853.4) v3@4991.11,3840.86 ; 4978.19,3835.67 cw(c4978.19,3817.56) 4991,3830.37 ccw(c4978.19,3817.56) 4978.19,3835.67 ; 4978.19,3835.67 ccw(c4978.19,3853.78) 4991,3840.97 cw(c4978.19,3853.78) 4978.19,3835.67
  MidLayer2 w4: v1(2180.86,2325.04) 2217.66,2325.04 2225.16,2332.54 2356.48,2332.54 2378.9,2354.96 2394.44,2370.5 2415.56,2370.5 2444.35,2341.71 2740.65,2341.71 2749.44,2350.5 2770.56,2350.5 2779.35,2341.71 3203.19,2341.71 3206.86,2338.04 3270.98,2338.04 3307.98,2375.04 4891.19,2375.04 4907.86,2391.71 v1(4907.86,2482.37) ; v1@2184.75,2321.15 cw(c2194.14,2311.76) 2194.14,2325.04 cw(c2194.14,2338.32) v1@2184.75,2328.93 ; v1@2187.57,2318.32 cw(c2203.79,2302.11) 2203.79,2325.04 cw(c2203.79,2347.98) v1@2187.57,2331.76 ; v1@4901.14,2475.66 cw(c4884.92,2459.44) 4907.86,2459.44 cw(c4930.79,2459.44) v1@4914.57,2475.66 ; v1@4903.97,2478.49 cw(c4894.58,2469.1) 4907.86,2469.1 cw(c4921.14,2469.1) v1@4911.75,2478.49
  Bottom Layer w4: R19.2@-350.5,2544.37 cw(c-370.74,2544.07) -356.43,2529.75 cw(c-343.14,2516.47) R19.2@-341.83,2535.21 ; R19.2@-350.22,2535.96 cw(c-342.33,2528.07) R19.2@-341.55,2539.2 ; R19.2@-349.74,2536.44 ccw(c-357.56,2544.27) R19.2@-346.5,2544.43 ; R19.2@-341.18,2545 -356.18,2530 -389,2530 -422,2497 -422,2390.81 -343.21,2312.02 2112.02,2312.02 2125.04,2325.04 v1(2180.86,2325.04) ; v1@2174.14,2318.32 ccw(c2157.92,2302.11) 2157.92,2325.04 ccw(c2157.92,2347.98) v1@2174.14,2331.76 ; v1@2176.97,2321.15 ccw(c2167.58,2311.76) 2167.58,2325.04 ccw(c2167.58,2338.32) v1@2176.97,2328.93
CODEC.I2S_MCLK: R20.1 U8.G13 | length 13754.6
  Top Layer w4: v3(5350.63,4465.59) U8.G13@5370.31,4445.91 ; U8.G13@5362.81,4445.91 ccw(c5344.71,4445.91) 5357.51,4458.71 ccw(c5370.31,4471.51) U8.G13@5370.31,4453.41 ; U8.G13@5362.97,4445.91 ccw(c5345.25,4445.91) 5357.78,4458.44 ccw(c5370.31,4470.97) U8.G13@5370.31,4453.25 ; 5363.43,4452.79 cw(c5376.24,4465.59) 5358.13,4465.59 ccw(c5376.24,4465.59) 5363.43,4452.79 ; 5363.43,4452.79 ccw(c5350.63,4439.98) 5350.63,4458.09 cw(c5350.63,4439.98) 5363.43,4452.79
  MidLayer1 w4: v4(475,2945) 497.19,2945 ; v4@479.3,2941.09 cw(c488.14,2933.04) 488.14,2945 cw(c488.14,2956.96) v4@479.3,2948.91 ; v4@482.26,2938.4 cw(c497.19,2924.81) 497.19,2945 ; v4@482.26,2951.6 ccw(c497.19,2965.19) 497.19,2945 ; v1@5408.14,4956.76 ccw(c5391.13,4973.77) 5415.19,4973.77 ; v1@5410.97,4953.93 ccw(c5400.79,4964.11) 5415.19,4964.11 ; v1(5414.86,4950.04) 5415.19,4950.04 5415.19,5000.04 5495.86,5080.71 5495.86,5115.73 5470.5,5141.08 5470.5,5180 5470.5,5247.02 5491.76,5268.28 5505.19,5281.71 5573.52,5350.04 5674.19,5450.71 5674.19,5548.13 5694,5567.94 5694,6154.37 5615,6233.37 4825,6233.37 4802,6256.37 4802,6650.37 4713.37,6739 1836.63,6739 1821,6723.37 1821,6589 1890,6520 1890,6433.18 1840.19,6383.37 1370,6383.37 1265.19,6278.56 1265.19,5010.19 1245,4990 601.31,4990 590.19,4978.88 590.19,4680.39 198.19,4288.39 198.19,3866.37 181.86,3850.04 181.86,3497.02 127.18,3442.35 127.18,3408.07 137.75,3397.5 177.5,3397.5 240,3460 610,3460 619,3451 619,3370 584,3335 535,3335 495,3295 495,3230 513.61,3211.39 513.61,2961.42 497.19,2945 ; 5415.19,4962.53 ccw(c5427.35,4962.53) v1@5418.75,4953.93 ; 5415.19,4972.18 ccw(c5437,4972.18) v1@5421.58,4956.76
  MidLayer2 w4: 5339.24,4479.17 cw(c5349.17,4489.1) 5335.12,4489.1 5335.12,4582.64 5335.12,4710 5335.12,4720 5335.12,4724.74 5335.12,4774.99 5378.52,4818.39 5378.52,4858.04 5365.19,4871.37 5365.19,4933.37 5381.86,4950.04 v1(5414.86,4950.04) ; v3@5343.16,4466.24 ccw(c5325.12,4467.82) 5338.99,4479.46 ccw(c5352.86,4491.1) v3@5351.28,4473.06 ; v1@5408.14,4943.32 ccw(c5391.93,4927.11) 5391.93,4950.04 ccw(c5391.93,4972.98) v1@5408.14,4956.76 ; v1@5410.97,4946.15 ccw(c5401.58,4936.76) 5401.58,4950.04 ccw(c5401.58,4963.32) v1@5410.97,4953.93
  Bottom Layer w4: R20.1@-347.77,2888.41 ccw(c-363.68,2872.5) -363.68,2895 ccw(c-363.68,2917.5) R20.1@-347.77,2901.59 ; R20.1@-344.94,2891.24 ccw(c-354.02,2882.16) -354.02,2895 ccw(c-354.02,2907.84) R20.1@-344.94,2898.76 ; R20.1@-341.18,2895 -440,2895 -443.48,2898.48 -443.48,3030.06 -431.5,3042.04 377.96,3042.04 v4(475,2945) ; v4@465.19,2945 ccw(c441.5,2945) 458.25,2961.75 ccw(c475,2978.5) v4@475,2954.81 ; v4@469.19,2945 ccw(c455.16,2945) 465.08,2954.92 ccw(c475,2964.84) v4@475,2950.81
CODEC.I2S_WCLK: R18.1 U8.AF13 | length 7585
  Top Layer w4: v1@5358.47,3406.76 ccw(c5342.26,3422.98) 5365.19,3422.98 ccw(c5388.13,3422.98) v1@5371.91,3406.76 ; v1@5361.3,3403.93 ccw(c5351.91,3413.32) 5365.19,3413.32 ccw(c5378.47,3413.32) v1@5369.08,3403.93 ; U8.AF13@5365.01,3692.57 cw(c5352.21,3679.77) 5370.31,3679.77 cw(c5388.42,3679.77) U8.AF13@5375.62,3692.57 ; U8.AF13@5365.12,3692.68 cw(c5352.59,3680.15) 5370.31,3680.15 cw(c5388.04,3680.15) U8.AF13@5375.51,3692.68 ; v1(5365.19,3400.04) 5365.19,3431.51 5356.7,3440 5356.7,3517.89 5373.52,3534.71 5373.52,3622.79 5370.31,3626 5370.31,3660 5370.31,3670 U8.AF13@5370.31,3697.87
  MidLayer1 w4: v1@5333.47,3284.99 cw(c5317.26,3268.77) 5340.19,3268.77 cw(c5363.13,3268.77) v1@5346.91,3284.99 ; v1@5336.3,3287.82 cw(c5326.91,3278.43) 5340.19,3278.43 cw(c5353.47,3278.43) v1@5344.08,3287.82 ; v1(5340.19,3291.71) 5340.19,3265.69 5390.86,3215.02 5390.86,3163.39 5348.19,3120.73 5348.19,3033.71 5372.52,3009.37 5390.19,2991.71 5390.19,2965.04 v4(5365.19,2940.04) ; v4@5365.19,2945.85 ccw(c5365.19,2959.88) 5375.11,2949.96 ccw(c5385.03,2940.04) v4@5371,2940.04 ; v4@5365.19,2949.85 ccw(c5365.19,2973.54) 5381.94,2956.79 ccw(c5398.69,2940.04) v4@5375,2940.04
  MidLayer2 w4: v1@-374.86,2948.43 ccw(c-391.08,2964.64) -368.14,2964.64 ccw(c-345.21,2964.64) v1@-361.43,2948.43 ; v1@-372.03,2945.6 ccw(c-381.42,2954.99) -368.14,2954.99 ccw(c-354.86,2954.99) v1@-364.25,2945.6 ; v1(-368.14,2941.71) -368.14,3036.9 -363,3042.04 180.33,3042.04 415.37,2807 563.31,2807 626.31,2870 2110.9,2870 2140.05,2840.85 2172.66,2840.85 2215.19,2883.37 2290.19,2883.37 2308.56,2865 2453.29,2865 2488.33,2900.04 4673.52,2900.04 4690.19,2916.71 4715.19,2916.71 4723.52,2908.37 5005,2908.37 5018.37,2895 v4(5085,2895) ; v4@5078.06,2888.06 ccw(c5061.31,2871.31) 5061.31,2895 ccw(c5061.31,2918.69) v4@5078.06,2901.94 ; v4@5080.89,2890.89 ccw(c5070.97,2880.97) 5070.97,2895 ccw(c5070.97,2909.03) v4@5080.89,2899.11
  Bottom Layer w4: v1@-364.25,2937.82 cw(c-354.86,2928.43) -354.86,2941.71 cw(c-354.86,2954.99) v1@-364.25,2945.6 ; v1@-361.43,2934.99 cw(c-345.21,2918.77) -345.21,2941.71 cw(c-345.21,2964.64) v1@-361.43,2948.43 ; v1@-359.24,2941.71 ccw(c-359.24,2960.54) R18.1@-345.16,2948.04 ; v1@-356.92,2941.71 cw(c-356.92,2928.77) R18.1@-347.77,2937.92 ; R18.1@-348.15,2950.69 cw(c-368.14,2968.44) v1(-368.14,2941.71) -341.18,2941.71 -341.18,2944.51 R18.1@-341.18,2945 ; v4(5085,2895) 5100.81,2910.81 5189.31,2910.81 5229.31,2950.81 5250.69,2950.81 5268.62,2932.88 5317.88,2932.88 5325,2940 v4@5365.15,2940 ; v1(5340.19,3291.71) 5361.96,3291.71 ; 5341.41,2940 ccw(c5341.41,2963.83) v4@5358.25,2946.98 ; 5341.6,2940 cw(c5341.6,2916.45) v4@5358.25,2933.1 ; v1@5344.22,3287.97 cw(c5352.79,3280.02) 5352.79,3291.71 cw(c5352.79,3303.4) v1@5344.22,3295.45 ; v1@5347.16,3285.25 cw(c5361.96,3271.52) 5361.96,3291.71 ; v1@5347.16,3298.17 ccw(c5361.96,3311.9) 5361.96,3291.71 ; 5351.06,2940 ccw(c5351.06,2954.17) v4@5361.08,2944.15 ; 5351.26,2940 cw(c5351.26,2926.11) v4@5361.08,2935.93 ; v1@5365.19,3390.54 cw(c5365.19,3367.61) 5381.41,3383.82 cw(c5397.63,3400.04) v1@5374.69,3400.04 ; v1@5365.19,3394.54 cw(c5365.19,3381.26) 5374.58,3390.65 cw(c5383.97,3400.04) v1@5370.69,3400.04 ; v1(5365.19,3400.04) 5390.19,3375.04 5390.19,3319.94 5361.96,3291.71
CODEC.SPI_CLK: U1.10 U8.A14 | length 9939.1
  Top Layer w4: v1(-450,2605) -395,2605 -391.77,2608.23 U1.10@-320,2608.23 ; v1@-446.11,2601.11 cw(c-436.72,2591.72) -436.72,2605 cw(c-436.72,2618.28) v1@-446.11,2608.89 ; v1@-443.28,2598.28 cw(c-427.07,2582.06) -427.07,2605 cw(c-427.07,2627.93) v1@-443.28,2611.72 ; U1.10@-339.74,2604.63 ccw(c-348.42,2595.95) -348.42,2608.23 ccw(c-348.42,2620.51) U1.10@-339.74,2611.83 ; v1(5390.19,4735) 5400.15,4725.04 5409.38,4725.04 ; U8.A14@5404.38,4687.43 ccw(c5391.58,4700.23) 5409.69,4700.23 ccw(c5427.79,4700.23) U8.A14@5414.99,4687.43 ; U8.A14@5404.49,4687.32 ccw(c5391.96,4699.85) 5409.69,4699.85 ccw(c5427.41,4699.85) U8.A14@5414.88,4687.32 ; U8.A14@5409.69,4682.13 5409.69,4710 5409.69,4720 5409.69,4724.74
  MidLayer1 w4: v1@-456.72,2598.28 ccw(c-472.94,2582.06) -472.94,2605 ccw(c-472.94,2627.93) v1@-456.72,2611.72 ; v1@-453.89,2601.11 ccw(c-463.28,2591.72) -463.28,2605 ccw(c-463.28,2618.28) v1@-453.89,2608.89 ; v1(-450,2605) -482.19,2605 -492.19,2615 -492.19,3021.25 -463.39,3050.04 -463.39,3136.61 -450,3150 v1(-395,3150) ; v1@-401.72,3143.28 ccw(c-417.94,3127.06) -417.94,3150 ccw(c-417.94,3172.93) v1@-401.72,3156.72 ; v1@-398.89,3146.11 ccw(c-408.28,3136.72) -408.28,3150 ccw(c-408.28,3163.28) v1@-398.89,3153.89 ; v4@-11.94,3216.94 ccw(c-28.69,3233.69) -5,3233.69 ccw(c18.69,3233.69) v4@1.94,3216.94 ; v4@-9.11,3214.11 ccw(c-19.03,3224.03) -5,3224.03 ccw(c9.03,3224.03) v4@-0.89,3214.11 ; v4(-5,3210) -5,3275 -18.31,3288.31 -18.31,3741.5 15.19,3775 15.19,3833.37 31.86,3850.04 165.19,3850.04 190.19,3875.04 190.19,4291.71 581.86,4683.37 581.86,4981.86 598,4998 1213,4998 v4(1240,5025) v4@1241.69,5023.31 ; v4@1230.19,5025 cw(c1206.5,5025) 1223.25,5008.25 cw(c1240,4991.5) v4@1240,5015.19 ; v4@1234.19,5025 cw(c1220.16,5025) 1230.08,5015.08 cw(c1240,5005.16) v4@1240,5019.19 ; v1@5383.47,4741.72 ccw(c5367.26,4757.93) 5390.19,4757.93 ccw(c5413.13,4757.93) v1@5396.91,4741.72 ; v1@5386.3,4738.89 ccw(c5376.91,4748.28) 5390.19,4748.28 ccw(c5403.47,4748.28) v1@5394.08,4738.89 ; v1(5390.19,4735) 5390.19,4766.71 5423.52,4800.04 5423.52,4903.71 5428.19,4908.37 5453.52,4908.37 5461.15,4916 5475.65,4916 5483.27,4908.37 5506.86,4908.37 5514.75,4900.48 5514.75,4870 5499.75,4855 v4(5460,4855) ; v4@5464.11,4850.89 cw(c5474.03,4840.97) 5474.03,4855 cw(c5474.03,4869.03) v4@5464.11,4859.11 ; v4@5466.94,4848.06 cw(c5483.69,4831.31) 5483.69,4855 cw(c5483.69,4878.69) v4@5466.94,4861.94
  MidLayer2 w4: v1(-395,3150) -335,3210 v4(-5,3210) ; v1@-395,3155.5 ccw(c-395,3168.78) -385.61,3159.39 ccw(c-376.22,3150) v1@-389.5,3150 ; v1@-395,3159.5 ccw(c-395,3182.43) -378.78,3166.22 ccw(c-362.57,3150) v1@-385.5,3150 ; v4@-11.94,3203.06 ccw(c-28.69,3186.31) -28.69,3210 ccw(c-28.69,3233.69) v4@-11.94,3216.94 ; v4@-9.11,3205.89 ccw(c-19.03,3195.97) -19.03,3210 ccw(c-19.03,3224.03) v4@-9.11,3214.11 ; v4(4080,4980) 4165,4980 4275,4870 4314.88,4870 4328,4856.87 4355.77,4856.87 4366.02,4867.13 4366.02,4881.62 4320.62,4927.02 4309.6,4927.02 4299.35,4937.28 4299.35,4955.62 4313.73,4970 ; v4@4084.11,4975.89 cw(c4094.03,4965.97) 4094.03,4980 cw(c4094.03,4994.03) v4@4084.11,4984.11 ; v4@4086.94,4973.06 cw(c4103.69,4956.31) 4103.69,4980 cw(c4103.69,5003.69) v4@4086.94,4986.94 ; v4(4330,4970) 4313.73,4970 ; 4313.74,4970 cw(c4313.74,4961.42) 4321.32,4965.42 ccw(c4313.74,4961.42) 4313.74,4970 ; 4313.74,4970 ccw(c4313.74,4978.58) 4321.32,4974.58 cw(c4313.74,4978.58) 4313.74,4970
  Bottom Layer w4: v4(1240,5025) 1320.45,5025 1369.92,4975.54 3808.99,4975.54 3817.98,4966.54 3871.54,4966.54 3895,4990 4070,4990 v4(4080,4980) ; v4(4330,4970) 4363.65,4970 4377.35,4983.71 4948.21,4983.71 4975.38,4956.54 5037.65,4956.54 5069.31,4924.87 5110.67,4924.87 5168.84,4983.04 5331.54,4983.04 5365.52,4949.06 5365.52,4854.73 5402.75,4817.5 5422.5,4817.5 v4(5460,4855) ; v4@4334.11,4965.89 cw(c4344.03,4955.97) 4344.03,4970 cw(c4344.03,4984.03) v4@4334.11,4974.11 ; v4@4336.94,4963.06 cw(c4353.69,4946.31) 4353.69,4970 cw(c4353.69,4993.69) v4@4336.94,4976.94 ; v4@5450.19,4855 cw(c5426.5,4855) 5443.25,4838.25 cw(c5460,4821.5) v4@5460,4845.19 ; v4@5454.19,4855 cw(c5440.16,4855) 5450.08,4845.08 cw(c5460,4835.16) v4@5460,4849.19
CODEC.SPI_CS_N: U1.11 U8.AE9 | length 7988.4
  Top Layer w4: v1(-455,2575) -423.03,2575 -415,2583.03 U1.11@-320,2583.03 ; v1@-451.11,2571.11 cw(c-441.72,2561.72) -441.72,2575 cw(c-441.72,2588.28) v1@-451.11,2578.89 ; v1@-448.28,2568.28 cw(c-432.07,2552.06) -432.07,2575 cw(c-432.07,2597.93) v1@-448.28,2581.72 ; U1.11@-339.74,2579.43 ccw(c-348.42,2570.75) -348.42,2583.03 ccw(c-348.42,2595.31) U1.11@-339.74,2586.63 ; v1(5114.19,3450.04) 5133.86,3450.04 ; v1@5121.63,3444.14 cw(c5133.86,3434.44) 5133.86,3450.04 ; v1@5121.63,3455.95 ccw(c5133.86,3465.65) 5133.86,3450.04 ; U8.AE9@5205.49,3737.24 cw(c5187.77,3737.24) 5200.3,3724.71 ; U8.AE9@5212.83,3729.9 ccw(c5212.83,3712.17) 5200.3,3724.71 ; 5133.86,3450.04 5189.57,3505.76 5198.02,3514.21 5198.02,3573.85 5193.02,3578.85 5193.02,3613.23 5197.33,3617.53 5197.33,3660 5197.33,3670 5197.33,3717.53 cw(c5207.48,3717.53) 5200.3,3724.71
  MidLayer1 w4: v1(3313.19,2339.71) 3342.29,2368.81 3391.69,2368.81 3615.37,2592.49 3680,2657.12 ; v1@3313.19,2345.21 ccw(c3313.19,2358.49) 3322.58,2349.1 ccw(c3331.97,2339.71) v1@3318.69,2339.71 ; v1@3313.19,2349.21 ccw(c3313.19,2372.14) 3329.41,2355.93 ccw(c3345.63,2339.71) v1@3322.69,2339.71 ; v1@3673.3,2673.27 cw(c3657.21,2657.13) 3680,2657.13 ; v1@3676.12,2676.1 cw(c3666.81,2666.76) 3680,2666.76 cw(c3693.19,2666.76) v1@3683.88,2676.1 ; v1(3680,2680) 3680,2657.12 ; v1@3686.7,2673.27 ccw(c3702.79,2657.13) 3680,2657.13 ; 5056.98,2750.37 cw(c5056.98,2725.16) v1@5074.81,2742.99 ; 5060.2,2750.37 ccw(c5060.2,2771.03) v1@5074.81,2756.43 ; 5066.64,2750.37 cw(c5066.64,2734.82) v1@5077.64,2745.82 ; 5069.86,2750.37 ccw(c5069.86,2761.38) v1@5077.64,2753.6 ; v1(5081.52,2749.71) 5081.52,2750.37 5045.82,2750.37 4990.19,2806 4990.19,3138.33 5031.86,3180 5031.86,3283.37 5015.19,3300.04 4997.19,3318.04 4997.19,3373.43 5044.26,3420.5 5109.69,3420.5 5114.19,3425 v1(5114.19,3450.04) ; v1@5107.47,3443.32 cw(c5091.26,3427.11) 5114.19,3427.11 cw(c5137.13,3427.11) v1@5120.91,3443.32 ; v1@5110.3,3446.15 cw(c5100.91,3436.76) 5114.19,3436.76 cw(c5127.47,3436.76) v1@5118.08,3446.15
  MidLayer2 w4: v1@-464.5,2575 cw(c-487.44,2575) -471.22,2558.78 cw(c-455,2542.56) v1@-455,2565.5 ; v1@-460.5,2575 cw(c-473.78,2575) -464.39,2565.61 cw(c-455,2556.22) v1@-455,2569.5 ; v1(-455,2575) -485,2545 -485,2460 -382.71,2357.71 -122.29,2357.71 -110,2370 -90,2370 -28.37,2308.37 1631.86,2308.37 1640.19,2300.04 2203.98,2300.04 2228.48,2324.54 2359.79,2324.54 2387.5,2352.25 2397.75,2362.5 2412.25,2362.5 2441.37,2333.37 2743.63,2333.37 2752.75,2342.5 2767.25,2342.5 2776.37,2333.37 3198.52,2333.37 3201.9,2330 3275,2330 3284.71,2339.71 v1(3313.19,2339.71) ; v1@3306.47,2332.99 ccw(c3290.26,2316.77) 3290.26,2339.71 ccw(c3290.26,2362.64) v1@3306.47,2346.43 ; v1@3309.3,2335.82 ccw(c3299.91,2326.43) 3299.91,2339.71 ccw(c3299.91,2352.99) v1@3309.3,2343.6 ; v1(3680,2680) 3758.71,2758.71 4078,2758.71 4145,2691.71 4848.52,2691.71 4906.52,2749.71 v1(5081.52,2749.71) ; v1@3680,2685.5 ccw(c3680,2698.78) 3689.39,2689.39 ccw(c3698.78,2680) v1@3685.5,2680 ; v1@3680,2689.5 ccw(c3680,2712.43) 3696.22,2696.22 ccw(c3712.43,2680) v1@3689.5,2680 ; v1@5074.81,2742.99 ccw(c5058.59,2726.77) 5058.59,2749.71 ccw(c5058.59,2772.64) v1@5074.81,2756.43 ; v1@5077.64,2745.82 ccw(c5068.25,2736.43) 5068.25,2749.71 ccw(c5068.25,2762.99) v1@5077.64,2753.6
CODEC.SPI_DIN: U1.12 U8.T4 | length 7725.8
  Top Layer w4: v1(-370,2555) -367.17,2557.83 U1.12@-320,2557.83 ; v1@-366.11,2551.11 cw(c-349.88,2534.88) -349.88,2557.83 ; v1@-363.28,2548.28 cw(c-340.22,2525.22) U1.12@-340.22,2557.83 ; v1@-363.28,2561.72 ccw(c-353.91,2571.09) -353.91,2557.83 ; U1.12@-339.74,2554.24 ccw(c-348.42,2545.55) -348.42,2557.83 ccw(c-348.42,2570.11) U1.12@-339.74,2561.43 ; v3(4996.3,4071.89) U8.T4@5015.98,4091.57 ; U8.T4@5008.48,4091.57 cw(c4990.38,4091.57) 5003.18,4078.77 cw(c5015.98,4065.97) U8.T4@5015.98,4084.07 ; U8.T4@5008.64,4091.57 cw(c4990.92,4091.57) 5003.45,4079.04 cw(c5015.98,4066.51) U8.T4@5015.98,4084.23 ; 5009.1,4084.69 cw(c4996.3,4097.5) 4996.3,4079.39 ccw(c4996.3,4097.5) 5009.1,4084.69 ; 5009.1,4084.69 ccw(c5021.91,4071.89) 5003.8,4071.89 cw(c5021.91,4071.89) 5009.1,4084.69
  MidLayer1 w4: v1@2753.28,2318.28 cw(c2737.06,2302.06) 2760,2302.06 cw(c2782.93,2302.06) v1@2766.72,2318.28 ; v1@2756.11,2321.11 cw(c2746.72,2311.72) 2760,2311.72 cw(c2773.28,2311.72) v1@2763.89,2321.11 ; v1(2760,2325) 2760,2224.5 2829,2155.5 3157.65,2155.5 3189.18,2187.03 3331.86,2329.71 3331.86,2338.37 3348.13,2354.65 3354.29,2360.81 3395,2360.81 3706.86,2672.67 3706.86,3191.71 4041.19,3526.04 4068.19,3526.04 4094.23,3500 4123.48,3500 4151.48,3528 4206.84,3528 4232.19,3553.35 4232.19,3769.71 4210.19,3791.71 4184.8,3791.71 4173.52,3802.98 4173.52,3878.52 4240,3945 4240,3995.93 4343.78,4099.71 4626.84,4099.71 4630.84,4095.71 4702.4,4095.71 4710.61,4103.92 4731.99,4103.92 4740.2,4095.71 4752.84,4095.71 4756.84,4091.71 4785,4091.71 4809.84,4091.71 4829.66,4071.89 4860,4071.89 4870,4071.89 4918.62,4071.89 v3(4996.3,4071.89) ; v3@4991,4066.59 ccw(c4978.19,4053.78) 4978.19,4071.89 ccw(c4978.19,4090) v3@4991,4077.19 ; v3@4991.11,4066.7 ccw(c4978.57,4054.16) 4978.57,4071.89 ccw(c4978.57,4089.62) v3@4991.11,4077.08
  Bottom Layer w4: v1@-376.72,2548.28 ccw(c-392.94,2532.06) -392.94,2555 ccw(c-392.94,2577.93) v1@-376.72,2561.72 ; v1@-373.89,2551.11 ccw(c-383.28,2541.72) -383.28,2555 ccw(c-383.28,2568.28) v1@-373.89,2558.89 ; v1(-370,2555) -415,2555 -430,2540 -430,2387.5 -346.52,2304.02 2207.96,2304.02 2229.44,2325.5 2759.5,2325.5 v1(2760,2325)
CODEC.SPI_DOUT: U1.9 U8.AE2 | length 7513.4
  Top Layer w4: U1.9@-320,2633.43 -268.17,2633.42 -252.25,2617.5 -188.27,2617.5 v1(-159.81,2589.04) ; U1.9@-300.26,2629.83 cw(c-291.58,2621.15) -291.58,2633.42 cw(c-291.58,2645.71) U1.9@-300.26,2637.02 ; v1@-169.31,2589.04 ccw(c-192.24,2589.04) -176.03,2605.26 ccw(c-159.81,2621.48) v1@-159.81,2598.54 ; v1@-165.31,2589.04 ccw(c-178.59,2589.04) -169.2,2598.43 ccw(c-159.81,2607.82) v1@-159.81,2594.54 ; 4866.04,3474.19 4852.19,3488.04 ; v1@4872.36,3458.37 ccw(c4849.42,3458.37) 4865.64,3474.59 ccw(c4881.86,3490.81) v1@4881.86,3467.87 ; v1@4876.36,3458.37 ccw(c4863.08,3458.37) 4872.47,3467.76 ccw(c4881.86,3477.15) v1@4881.86,3463.87 ; v1(4881.86,3458.37) 4852.19,3488.04 ; 4852.19,3488.04 4852.19,3587.04 4870.15,3605 4885,3605 4921.74,3641.74 4921.74,3655.26 4921.74,3660 4921.74,3670 4921.74,3717.53 ; 4921.74,3717.53 cw(c4931.89,3717.53) 4924.71,3724.71 ; 4921.74,3717.53 cw(c4931.89,3717.53) 4924.71,3724.71 ; 4924.71,3724.71 cw(c4937.24,3712.17) 4937.24,3729.9 ccw(c4937.24,3712.17) 4924.71,3724.71 ; 4924.71,3724.71 ccw(c4912.17,3737.24) 4929.9,3737.24 cw(c4912.17,3737.24) 4924.71,3724.71
  MidLayer1 w4: 4857,2418.57 4857.19,2418.37 ; 4857,2494 4857.19,2494 ; v1@4875.14,3451.66 cw(c4858.92,3435.44) 4881.86,3435.44 cw(c4904.79,3435.44) v1@4888.57,3451.66 ; v1@4877.97,3454.49 cw(c4868.58,3445.1) 4881.86,3445.1 cw(c4895.14,3445.1) v1@4885.75,3454.49 ; v1(4881.86,3458.37) 4881.86,3358.98 4906.52,3334.32 4906.52,3266.37 4898.52,3258.37 4898.52,2732.04 4857.19,2690.71 4857.19,2521 4857.19,2494 ; v1@4899.36,2366.71 ccw(c4876.42,2366.71) 4892.64,2382.93 ; v1@4903.36,2366.71 ccw(c4890.08,2366.71) 4899.47,2376.1 ccw(c4908.86,2385.49) v1@4908.86,2372.21 ; v1@4908.86,2376.21 cw(c4908.86,2399.14) 4892.64,2382.93 ; 4857.19,2418.37 4892.64,2382.93 ; 4857.19,2418.37 4857.19,2494
  MidLayer2 w4: v1@2405,2335.5 cw(c2405,2312.56) 2421.22,2328.78 cw(c2437.43,2345) v1@2414.5,2345 ; v1@2405,2339.5 cw(c2405,2326.22) 2414.39,2335.61 cw(c2423.78,2345) v1@2410.5,2345 ; v1(2405,2345) 2442.5,2307.5 3364.32,2307.5 3365.19,2308.37 3423.52,2366.71 v1(4908.86,2366.71)
  Bottom Layer w4: v1@-166.53,2582.32 cw(c-182.74,2566.11) -159.81,2566.11 cw(c-136.87,2566.11) v1@-153.09,2582.32 ; v1@-163.7,2585.15 cw(c-173.09,2575.76) -159.81,2575.76 cw(c-146.53,2575.76) v1@-155.92,2585.15 ; v1(-159.81,2589.04) -159.81,2337.83 -150,2328.02 2101.29,2328.02 2148.31,2375.04 2245,2375.04 2275.04,2345 v1(2405,2345) ; v1@2398.28,2338.28 ccw(c2382.06,2322.06) 2382.06,2345 ccw(c2382.06,2367.93) v1@2398.28,2351.72 ; v1@2401.11,2341.11 ccw(c2391.72,2331.72) 2391.72,2345 ccw(c2391.72,2358.28) v1@2401.11,2348.89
